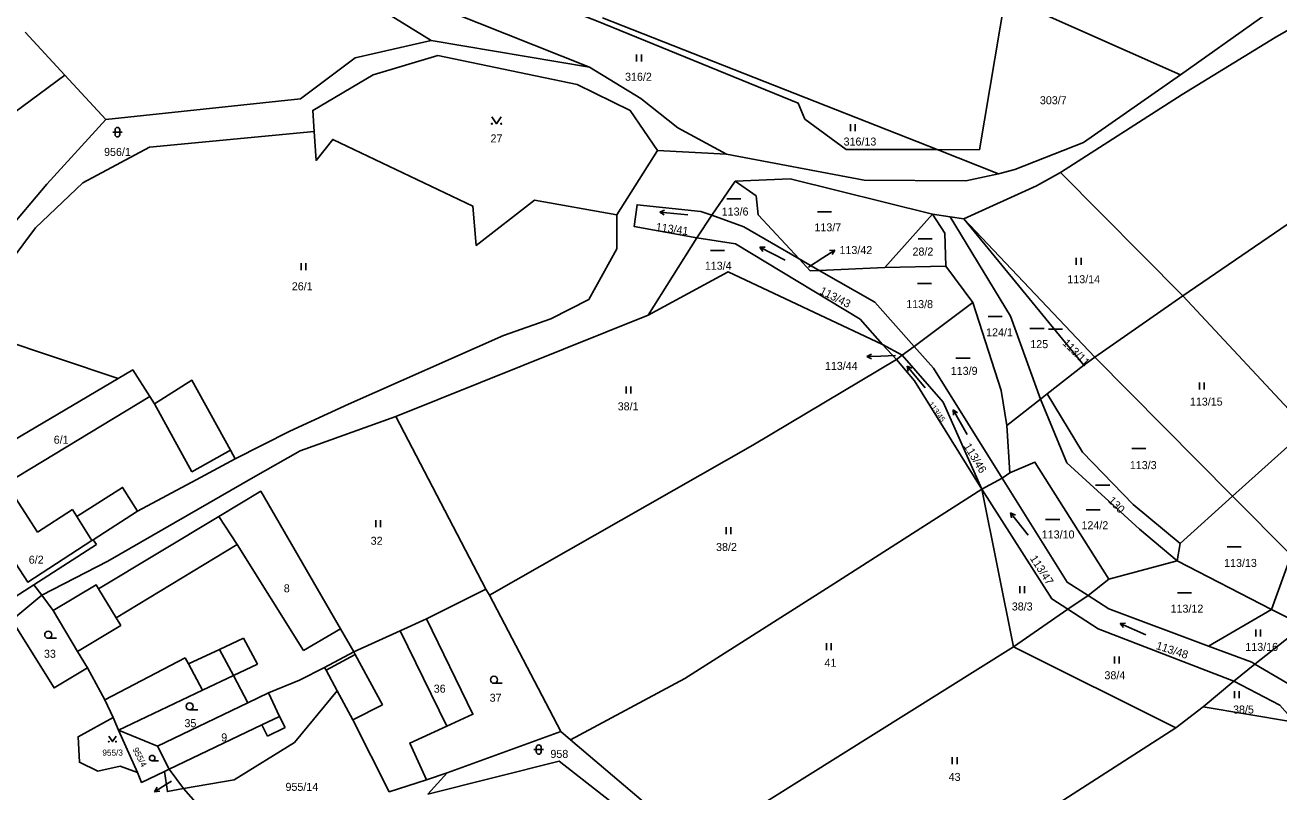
# Model space of a CAD drawing. Extents: x -751333 to -746055, y -1133395 to -1129777.
# Drawn here: x -747812.8 to -747546.5, y -1130986.6 to -1130823.7 of the extents above; entities that cross this region are included whole.
import ezdxf

# ---------------------------------------------------------------- set-up
doc = ezdxf.new("R2010")
doc.units = 0
for name, color, linetype in [('Hranice parcel', 7, 'Continuous'), ('Parcelní čísla', 7, 'Continuous'), ('Pop  PČ popisy', 7, 'Continuous'), ('Vnitřní kresba', 7, 'Continuous'), ('Značky kultur', 7, 'Continuous')]:
    doc.layers.add(name, color=color, linetype=linetype)

msp = doc.modelspace()

# ---------------------------------------------------------------- linework, layer by layer
at = {"layer": 'Hranice parcel'}
for p, q in [((-747567.45, -1130834.27), (-747601.44, -1130819.19)), ((-747690.17, -1130822.16), (-747619.1, -1130850.16)), ((-747812.81, -1130825.22), (-747804.38, -1130834.32)), ((-747692.92, -1130832.64), (-747726.57, -1130826.97)), ((-747804.38, -1130834.32), (-747840.03, -1130860.79)), ((-747804.38, -1130834.32), (-747795.63, -1130843.76)), ((-747687.14, -1130864.03), (-747678.53, -1130850.34)), ((-747678.53, -1130850.34), (-747663.88, -1130851.09)), ((-747606.08, -1130855.29), (-747619.1, -1130850.16)), ((-747566.95, -1130881.22), (-747592.89, -1130855.02)), ((-747666.96, -1130864.06), (-747662, -1130856.84)), ((-747670.15, -1130868.87), (-747666.96, -1130864.06)), ((-747620.11, -1130863.87), (-747630.22, -1130875.23)), ((-747620.11, -1130863.87), (-747616.32, -1130864.44)), ((-747616.32, -1130864.44), (-747613.42, -1130864.85)), ((-747585.62, -1130894.26), (-747613.42, -1130864.85)), ((-747613.42, -1130864.85), (-747587.99, -1130895.92)), ((-747670.15, -1130868.87), (-747680.49, -1130885.34)), ((-747648.43, -1130873.34), (-747644.19, -1130875.8)), ((-747644.19, -1130875.8), (-747630.22, -1130875.23)), ((-747630.22, -1130875.23), (-747617.27, -1130874.92)), ((-747611.5, -1130882.62), (-747617.27, -1130874.92)), ((-747585.62, -1130894.26), (-747566.95, -1130881.22)), ((-747540.5, -1130909.52), (-747566.95, -1130881.22)), ((-747624, -1130891.96), (-747611.5, -1130882.62)), ((-747734.07, -1130906.85), (-747680.49, -1130885.34)), ((-747825.73, -1130887.83), (-747793.01, -1130898.76)), ((-747627.71, -1130894.75), (-747630.73, -1130891.53)), ((-747630.73, -1130891.53), (-747626.52, -1130893.83)), ((-747626.52, -1130893.83), (-747624, -1130891.96)), ((-747627.71, -1130894.75), (-747626.52, -1130893.83)), ((-747585.62, -1130894.26), (-747587.99, -1130895.92)), ((-747556.37, -1130923.79), (-747585.62, -1130894.26)), ((-747587.99, -1130895.92), (-747595.75, -1130902.05)), ((-747604.33, -1130908.77), (-747597.18, -1130903.17)), ((-747597.18, -1130903.17), (-747595.75, -1130902.05)), ((-747714.93, -1130943.52), (-747734.07, -1130906.85)), ((-747603.65, -1130918.79), (-747604.33, -1130908.77)), ((-747556.37, -1130923.79), (-747540.5, -1130909.52)), ((-747605.27, -1130919.98), (-747603.65, -1130918.79)), ((-747609.63, -1130922.29), (-747605.27, -1130919.98)), ((-747609.63, -1130922.29), (-747602.88, -1130955.82)), ((-747567.53, -1130933.83), (-747556.37, -1130923.79)), ((-747810.2, -1130931.39), (-747802.76, -1130926.61)), ((-747798.33, -1130933.02), (-747788.95, -1130926.93)), ((-747810.92, -1130942.58), (-747797.65, -1130934.06)), ((-747798.61, -1130933.2), (-747798.33, -1130933.02)), ((-747797.65, -1130934.06), (-747798.33, -1130933.02)), ((-747567.53, -1130933.83), (-747568.14, -1130937.53)), ((-747568.14, -1130937.53), (-747582.67, -1130941.38)), ((-747548.12, -1130947.84), (-747568.14, -1130937.53)), ((-747809.25, -1130944.84), (-747810.92, -1130942.58)), ((-747587.06, -1130944.87), (-747582.67, -1130941.38)), ((-747809.25, -1130944.84), (-747806.85, -1130948.1)), ((-747727.56, -1130949.81), (-747714.93, -1130943.52)), ((-747714.21, -1130944.8), (-747714.93, -1130943.52)), ((-747699.04, -1130973.8), (-747714.21, -1130944.8)), ((-747591.34, -1130947.8), (-747587.06, -1130944.87)), ((-747602.88, -1130955.82), (-747591.34, -1130947.8)), ((-747561.51, -1130955.61), (-747548.12, -1130947.84)), ((-747544.17, -1130949.82), (-747548.12, -1130947.84)), ((-747551.66, -1130959.44), (-747542.97, -1130952.61)), ((-747670.43, -1130998.05), (-747602.88, -1130955.82)), ((-747602.88, -1130955.82), (-747568.39, -1130973)), ((-747749.19, -1130960.19), (-747743.01, -1130956.84)), ((-747556.12, -1130963.07), (-747551.66, -1130959.44)), ((-747562.63, -1130968.51), (-747556.12, -1130963.07)), ((-747765.48, -1130967.66), (-747784.66, -1130976.88)), ((-747568.39, -1130973), (-747562.63, -1130968.51)), ((-747794.11, -1130970.77), (-747792.94, -1130973.48)), ((-747788.92, -1130982.46), (-747792.94, -1130973.48)), ((-747792.94, -1130973.48), (-747784.66, -1130976.88)), ((-747723.14, -1130982.58), (-747699.04, -1130973.8)), ((-747696.99, -1130975.53), (-747699.04, -1130973.8)), ((-747784.66, -1130976.88), (-747782.22, -1130981.78)), ((-747670.43, -1130998.05), (-747696.99, -1130975.53)), ((-747783.2, -1130982.29), (-747782.22, -1130981.78)), ((-747782.22, -1130981.78), (-747779.16, -1130985.88)), ((-747727.55, -1130984.01), (-747723.14, -1130982.58)), ((-747727.26, -1130987.09), (-747723.14, -1130982.58)), ((-747774.01, -1130991.73), (-747779.16, -1130985.88))]:
    msp.add_line(p, q, dxfattribs=at)
for points in [[(-747592.89, -1130855.02), (-747567.07, -1130838.41), (-747547.35, -1130826.32), (-747527.53, -1130814.88), (-747492.89, -1130797.06), (-747472.69, -1130787.42), (-747441.69, -1130763.28), (-747417.46, -1130747.1), (-747393.87, -1130731.74)], [(-747566.95, -1130881.22), (-747540.53, -1130863.15), (-747518.65, -1130845.8), (-747451.1, -1130789.94), (-747421.34, -1130761.04), (-747390.31, -1130735.18)], [(-747726.57, -1130826.97), (-747749.62, -1130812.66), (-747757.07, -1130798.44), (-747753.28, -1130789.29)], [(-747751.97, -1130797.81), (-747746.34, -1130810.93), (-747722.32, -1130820.98), (-747692.92, -1130832.64)], [(-747518.4, -1130801.96), (-747535.86, -1130812.1), (-747550.62, -1130822.39), (-747567.45, -1130834.27)], [(-747619.1, -1130850.16), (-747638.4, -1130850.1), (-747647.23, -1130843.67), (-747648.62, -1130840.27), (-747691.42, -1130822.76), (-747716.64, -1130813.01), (-747715.36, -1130812.23)], [(-747619.1, -1130850.16), (-747610.15, -1130850.19), (-747604.68, -1130817.79)], [(-747795.63, -1130843.76), (-747754.3, -1130839.33), (-747742.68, -1130830.62), (-747726.57, -1130826.97)], [(-747678.53, -1130850.34), (-747684.28, -1130841.87), (-747695.55, -1130836.35), (-747725.17, -1130830.16), (-747738.86, -1130834.29), (-747751.71, -1130841.81), (-747751.43, -1130846.33)], [(-747692.92, -1130832.64), (-747682.03, -1130839.3), (-747674.17, -1130845.51), (-747663.88, -1130851.09)], [(-747567.45, -1130834.27), (-747588.01, -1130848.67), (-747602.62, -1130854.39), (-747606.08, -1130855.29)], [(-747831.64, -1130880.59), (-747825.65, -1130878.15), (-747808.21, -1130857.46), (-747795.63, -1130843.76)], [(-747751.43, -1130846.33), (-747786.35, -1130849.61), (-747800.53, -1130857.22), (-747810.62, -1130866.79), (-747823.91, -1130884.54), (-747825.73, -1130887.83)], [(-747687.14, -1130864.03), (-747704.65, -1130860.86), (-747717, -1130870.51), (-747717.72, -1130862.13), (-747747.45, -1130847.99), (-747751.02, -1130852.43), (-747751.43, -1130846.33)], [(-747663.88, -1130851.09), (-747634.6, -1130856.66), (-747613, -1130856.77), (-747606.08, -1130855.29)], [(-747613.42, -1130864.85), (-747598.03, -1130857.85), (-747592.89, -1130855.02)], [(-747662, -1130856.84), (-747650.32, -1130856.36), (-747620.11, -1130863.87)], [(-747648.43, -1130873.34), (-747657.11, -1130864.01), (-747657.53, -1130859.98), (-747662, -1130856.84)], [(-747670.15, -1130868.87), (-747683.44, -1130866.5), (-747682.82, -1130861.87), (-747669.33, -1130863.29), (-747666.96, -1130864.06)], [(-747768.2, -1130915.84), (-747756.58, -1130909.94), (-747744.11, -1130904.25), (-747711.23, -1130889.62), (-747701.16, -1130886.13), (-747693.1, -1130881.99), (-747687.11, -1130871.26), (-747687.14, -1130864.03)], [(-747666.96, -1130864.06), (-747660.13, -1130866.55), (-747648.43, -1130873.34)], [(-747617.27, -1130874.92), (-747617.49, -1130867.91), (-747620.11, -1130863.87)], [(-747597.18, -1130903.17), (-747603.54, -1130885.52), (-747616.32, -1130864.44)], [(-747630.73, -1130891.53), (-747635.43, -1130886.18), (-747661.9, -1130870.18), (-747670.15, -1130868.87)], [(-747648.43, -1130873.34), (-747646.1, -1130875.88), (-747644.19, -1130875.8)], [(-747680.49, -1130885.34), (-747663.47, -1130876.12), (-747630.73, -1130891.53)], [(-747644.19, -1130875.8), (-747632.37, -1130882.58), (-747624, -1130891.96)], [(-747604.33, -1130908.77), (-747605.55, -1130901.3), (-747611.5, -1130882.62)], [(-747624, -1130891.96), (-747619.89, -1130896.55), (-747605.27, -1130919.98)], [(-747714.21, -1130944.8), (-747658.27, -1130912.95), (-747627.71, -1130894.75)], [(-747609.63, -1130922.29), (-747623.92, -1130899.27), (-747627.71, -1130894.75)], [(-747609.63, -1130922.29), (-747617.8, -1130903.81), (-747626.52, -1130893.83)], [(-747786.33, -1130902.63), (-747789.93, -1130896.95), (-747793.01, -1130898.76)], [(-747793.01, -1130898.76), (-747820.31, -1130914.83), (-747821.04, -1130913.77), (-747826.88, -1130917.6)], [(-747768.2, -1130915.84), (-747769.2, -1130914.03), (-747777.39, -1130899.14), (-747785.31, -1130904.19), (-747786.33, -1130902.63)], [(-747568.14, -1130937.53), (-747576.11, -1130930.77), (-747591.59, -1130916.72), (-747597.18, -1130903.17)], [(-747595.75, -1130902.05), (-747588.22, -1130914.45), (-747577.5, -1130925.53), (-747567.53, -1130933.83)], [(-747734.07, -1130906.85), (-747754.36, -1130914.15), (-747764.38, -1130919.82), (-747795.26, -1130937.61), (-747809.25, -1130944.84)], [(-747788.95, -1130926.93), (-747776.49, -1130920.27), (-747768.2, -1130915.84)], [(-747582.67, -1130941.38), (-747598.35, -1130916.55), (-747603.65, -1130918.79)], [(-747822.35, -1130924.58), (-747816.84, -1130921.05), (-747810.2, -1130931.39)], [(-747802.76, -1130926.61), (-747801.79, -1130928.13), (-747792.11, -1130921.93), (-747788.95, -1130926.93)], [(-747605.27, -1130919.98), (-747591.5, -1130942.05), (-747587.06, -1130944.87)], [(-747743.01, -1130956.84), (-747745.82, -1130951.95), (-747762.77, -1130922.74), (-747771.66, -1130928.1), (-747797.2, -1130943.47), (-747797.72, -1130942.61), (-747806.85, -1130948.1)], [(-747696.99, -1130975.53), (-747672.66, -1130962.51), (-747641.8, -1130942.93), (-747609.63, -1130922.29)], [(-747591.34, -1130947.8), (-747594.77, -1130945.6), (-747609.63, -1130922.29)], [(-747548.12, -1130947.84), (-747543.96, -1130936.32), (-747556.37, -1130923.79)], [(-747810.92, -1130942.58), (-747816.91, -1130946.43), (-747824.59, -1130933.96), (-747819.12, -1130930.45)], [(-747819.12, -1130930.45), (-747816.13, -1130935.12), (-747816.51, -1130935.36), (-747812.22, -1130942.04), (-747798.61, -1130933.2)], [(-747809.25, -1130944.84), (-747815.62, -1130950.1), (-747806.65, -1130964.52), (-747799.54, -1130960.27)], [(-747587.06, -1130944.87), (-747582.62, -1130947.7), (-747561.51, -1130955.61)], [(-747806.85, -1130948.1), (-747801.65, -1130956.79), (-747799.54, -1130960.27)], [(-747556.12, -1130963.07), (-747584.92, -1130951.93), (-747591.34, -1130947.8)], [(-747727.56, -1130949.81), (-747733.16, -1130952.36), (-747743.01, -1130956.84)], [(-747727.55, -1130984.01), (-747731.13, -1130976.23), (-747723.26, -1130972.63), (-747717.69, -1130970.09), (-747727.56, -1130949.81)], [(-747561.51, -1130955.61), (-747552.29, -1130959.07), (-747551.66, -1130959.44)], [(-747799.54, -1130960.27), (-747795.87, -1130967.04), (-747794.11, -1130970.77)], [(-747792.94, -1130973.48), (-747775.11, -1130965.02), (-747768.52, -1130961.91), (-747765.48, -1130967.66)], [(-747765.48, -1130967.66), (-747761.14, -1130965.57), (-747754.52, -1130962.87), (-747749.19, -1130960.19)], [(-747746.53, -1130965.11), (-747748.88, -1130960.76), (-747749.19, -1130960.19)], [(-747551.66, -1130959.44), (-747542.61, -1130964.81), (-747533.86, -1130974.48), (-747529.57, -1130980.67)], [(-747533.76, -1130983.87), (-747538.28, -1130977.32), (-747546.35, -1130968.19), (-747556.12, -1130963.07)], [(-747779.16, -1130985.88), (-747768.38, -1130984.02), (-747755.59, -1130976.12), (-747746.53, -1130965.11)], [(-747746.53, -1130965.11), (-747743.17, -1130971.3), (-747735.45, -1130986.58), (-747727.55, -1130984.01)], [(-747562.63, -1130968.51), (-747544.05, -1130971.62), (-747534.58, -1130984.5)], [(-747788.92, -1130982.46), (-747792.6, -1130981.16), (-747797.32, -1130982.19), (-747801.28, -1130980.31), (-747801.56, -1130974.89), (-747794.11, -1130970.77)], [(-747647.48, -1131019.78), (-747615.24, -1131003.06), (-747568.39, -1130973)], [(-747641.15, -1131027.46), (-747677.24, -1130997.39), (-747699.35, -1130980.06), (-747727.26, -1130987.09)], [(-747783.2, -1130982.29), (-747788.06, -1130984.58), (-747788.92, -1130982.46)], [(-747779.16, -1130985.88), (-747782.56, -1130986.54), (-747783.2, -1130982.29)]]:
    msp.add_lwpolyline(points, dxfattribs=at)
at = {"layer": 'Pop  PČ popisy'}
for p, q in [((-747646.42, -1130875.1), (-747643.37, -1130873.12)), ((-747643.37, -1130873.12), (-747640.853, -1130871.486)), ((-747640.853, -1130871.486), (-747641.966, -1130871.611)), ((-747640.853, -1130871.486), (-747641.42, -1130872.451)), ((-747634.049, -1130894.115), (-747633.066, -1130893.579)), ((-747631.05, -1130894.01), (-747634.049, -1130894.115)), ((-747634.049, -1130894.115), (-747633.031, -1130894.58)), ((-747627.99, -1130893.91), (-747631.05, -1130894.01)), ((-747782.79, -1130984.99), (-747785.335, -1130986.58)), ((-747785.335, -1130986.58), (-747784.751, -1130985.625)), ((-747781.73, -1130984.34), (-747782.79, -1130984.99)), ((-747785.335, -1130986.58), (-747784.22, -1130986.474))]:
    msp.add_line(p, q, dxfattribs=at)
at = {"layer": 'Vnitřní kresba'}
for p, q in [((-747786.33, -1130902.63), (-747816.84, -1130921.05)), ((-747785.31, -1130904.19), (-747777.39, -1130918.63)), ((-747769.2, -1130914.03), (-747777.39, -1130918.63)), ((-747801.79, -1130928.13), (-747798.61, -1130933.2)), ((-747767.79, -1130934.01), (-747771.66, -1130928.1)), ((-747793.47, -1130949.63), (-747767.79, -1130934.01)), ((-747753.68, -1130956.54), (-747767.79, -1130934.01)), ((-747797.2, -1130943.47), (-747793.47, -1130949.63)), ((-747801.65, -1130956.79), (-747792.49, -1130951.26)), ((-747793.47, -1130949.63), (-747792.49, -1130951.26)), ((-747766.45, -1130953.93), (-747771.54, -1130956.35)), ((-747763.42, -1130959.49), (-747766.45, -1130953.93)), ((-747753.68, -1130956.54), (-747745.82, -1130951.95)), ((-747733.16, -1130952.36), (-747723.26, -1130972.63)), ((-747771.54, -1130956.35), (-747778.1, -1130959.43)), ((-747771.54, -1130956.35), (-747768.52, -1130961.91)), ((-747778.81, -1130958.12), (-747795.87, -1130967.04)), ((-747778.81, -1130958.12), (-747778.1, -1130959.43)), ((-747748.88, -1130960.76), (-747742.69, -1130957.41)), ((-747742.69, -1130957.41), (-747743.01, -1130956.84)), ((-747736.92, -1130968.11), (-747742.69, -1130957.41)), ((-747778.1, -1130959.43), (-747775.11, -1130965.02)), ((-747768.52, -1130961.91), (-747763.42, -1130959.49)), ((-747761.14, -1130965.57), (-747758.74, -1130970.57)), ((-747743.17, -1130971.3), (-747736.92, -1130968.11)), ((-747762.53, -1130972.38), (-747782.22, -1130981.78)), ((-747758.74, -1130970.57), (-747762.53, -1130972.38)), ((-747761.33, -1130974.79), (-747762.53, -1130972.38)), ((-747758.74, -1130970.57), (-747757.54, -1130972.91)), ((-747757.54, -1130972.91), (-747761.33, -1130974.79))]:
    msp.add_line(p, q, dxfattribs=at)
at = {"layer": 'Značky kultur'}
for p, q in [((-747682.931, -1130831.43), (-747682.931, -1130829.93)), ((-747681.93, -1130831.43), (-747681.93, -1130829.93)), ((-747637.491, -1130846.23), (-747637.491, -1130844.73)), ((-747636.49, -1130846.23), (-747636.49, -1130844.73)), ((-747794.181, -1130846.441), (-747792.179, -1130846.441)), ((-747793.681, -1130845.941), (-747793.681, -1130846.942)), ((-747792.679, -1130846.942), (-747792.679, -1130845.941)), ((-747663.768, -1130860.61), (-747660.768, -1130860.61)), ((-747678.02, -1130863.406), (-747676.996, -1130863.01)), ((-747672.053, -1130864.033), (-747678.02, -1130863.406)), ((-747678.02, -1130863.406), (-747677.1, -1130864.007)), ((-747644.548, -1130863.36), (-747641.548, -1130863.36)), ((-747656.744, -1130870.903), (-747655.646, -1130870.899)), ((-747651.398, -1130873.627), (-747656.744, -1130870.903)), ((-747656.744, -1130870.903), (-747656.101, -1130871.793)), ((-747623.168, -1130869.11), (-747620.168, -1130869.11)), ((-747667.278, -1130871.61), (-747664.278, -1130871.61)), ((-747589.561, -1130874.63), (-747589.561, -1130873.13)), ((-747588.56, -1130874.63), (-747588.56, -1130873.13)), ((-747754.201, -1130875.77), (-747754.201, -1130874.27)), ((-747753.2, -1130875.77), (-747753.2, -1130874.27)), ((-747623.278, -1130878.56), (-747620.278, -1130878.56)), ((-747608.298, -1130885.57), (-747605.298, -1130885.57)), ((-747599.418, -1130888.17), (-747596.418, -1130888.17)), ((-747595.498, -1130888.31), (-747592.498, -1130888.31)), ((-747615.128, -1130894.45), (-747612.128, -1130894.45)), ((-747621.656, -1130900.749), (-747625.513, -1130896.153)), ((-747625.513, -1130896.153), (-747625.269, -1130897.224)), ((-747625.513, -1130896.153), (-747624.501, -1130896.579)), ((-747685.151, -1130901.99), (-747685.151, -1130900.49)), ((-747684.15, -1130901.99), (-747684.15, -1130900.49)), ((-747563.381, -1130901.11), (-747563.381, -1130899.61)), ((-747562.38, -1130901.11), (-747562.38, -1130899.61)), ((-747612.711, -1130910.639), (-747615.711, -1130905.443)), ((-747615.711, -1130905.443), (-747615.657, -1130906.54)), ((-747615.711, -1130905.443), (-747614.788, -1130906.038)), ((-747577.788, -1130913.63), (-747574.788, -1130913.63)), ((-747585.468, -1130921.44), (-747582.468, -1130921.44)), ((-747599.807, -1130932.055), (-747603.501, -1130927.327)), ((-747603.501, -1130927.327), (-747603.294, -1130928.406)), ((-747603.501, -1130927.327), (-747602.504, -1130927.788)), ((-747587.498, -1130926.66), (-747584.498, -1130926.66)), ((-747738.331, -1130930.36), (-747738.331, -1130928.86)), ((-747737.33, -1130930.36), (-747737.33, -1130928.86)), ((-747596.078, -1130928.75), (-747593.078, -1130928.75)), ((-747663.891, -1130931.87), (-747663.891, -1130930.37)), ((-747662.89, -1130931.87), (-747662.89, -1130930.37)), ((-747557.528, -1130934.52), (-747554.528, -1130934.52)), ((-747601.561, -1130944.39), (-747601.561, -1130942.89)), ((-747600.56, -1130944.39), (-747600.56, -1130942.89)), ((-747568.068, -1130944.3), (-747565.068, -1130944.3)), ((-747580.243, -1130950.825), (-747579.146, -1130950.764)), ((-747574.762, -1130953.265), (-747580.243, -1130950.825)), ((-747580.243, -1130950.825), (-747579.554, -1130951.681)), ((-747807.883, -1130953.97), (-747806.133, -1130953.97)), ((-747551.411, -1130953.59), (-747551.411, -1130952.09)), ((-747550.41, -1130953.59), (-747550.41, -1130952.09)), ((-747642.631, -1130956.48), (-747642.631, -1130954.98)), ((-747641.63, -1130956.48), (-747641.63, -1130954.98)), ((-747581.471, -1130959.36), (-747581.471, -1130957.86)), ((-747580.47, -1130959.36), (-747580.47, -1130957.86)), ((-747713.223, -1130963.53), (-747711.473, -1130963.53)), ((-747555.951, -1130966.7), (-747555.951, -1130965.2)), ((-747554.95, -1130966.7), (-747554.95, -1130965.2)), ((-747777.863, -1130969.18), (-747776.113, -1130969.18)), ((-747704.731, -1130977.601), (-747702.729, -1130977.601)), ((-747704.231, -1130977.101), (-747704.231, -1130978.102)), ((-747703.229, -1130978.102), (-747703.229, -1130977.101)), ((-747785.815, -1130980), (-747784.467, -1130980)), ((-747615.891, -1130980.72), (-747615.891, -1130979.22)), ((-747614.89, -1130980.72), (-747614.89, -1130979.22))]:
    msp.add_line(p, q, dxfattribs=at)
for points in [[(-747713.68, -1130843.159), (-747712.68, -1130844.66), (-747711.68, -1130843.159)], [(-747795.02, -1130974.764), (-747794.25, -1130975.92), (-747793.48, -1130974.764)]]:
    msp.add_lwpolyline(points, dxfattribs=at)
for centre, radius in [((-747713.68, -1130844.659), 0.1), ((-747711.68, -1130844.659), 0.1), ((-747807.883, -1130953.22), 0.75), ((-747713.223, -1130962.78), 0.75), ((-747777.863, -1130968.43), 0.75), ((-747795.02, -1130975.92), 0.077), ((-747793.48, -1130975.92), 0.077), ((-747785.815, -1130979.422), 0.577)]:
    msp.add_circle(centre, radius, dxfattribs=at)
for centre, start, end in [((-747793.18, -1130845.941), 0, 180), ((-747793.18, -1130846.941), 180, 359.98789), ((-747703.73, -1130977.101), 0, 180), ((-747703.73, -1130978.101), 180, 359.98789)]:
    msp.add_arc(centre, 0.5, start, end, dxfattribs=at)

# ---------------------------------------------------------------- texts
at = {"layer": 'Parcelní čísla'}
for s, height, p in [('316/2', 1.7, (-747685.39, -1130835.52)), ('303/7', 1.7, (-747597.29, -1130840.51)), ('27', 1.7, (-747713.96, -1130848.62)), ('956/1', 1.7, (-747796.03, -1130851.49)), ('316/13', 1.7, (-747638.98, -1130849.29)), ('113/6', 1.7, (-747664.86, -1130864.16)), ('113/7', 1.7, (-747645.17, -1130867.51)), ('113/42', 1.7, (-747639.85, -1130872.34)), ('28/2', 1.7, (-747624.34, -1130872.66)), ('113/4', 1.7, (-747668.45, -1130875.67)), ('113/14', 1.7, (-747591.46, -1130878.54)), ('26/1', 1.7, (-747756.16, -1130880.04)), ('113/8', 1.7, (-747625.68, -1130883.82)), ('124/1', 1.7, (-747608.71, -1130889.82)), ('125', 1.7, (-747599.33, -1130892.33)), ('113/44', 1.7, (-747642.945, -1130896.948)), ('113/9', 1.7, (-747616.22, -1130898)), ('113/15', 1.7, (-747565.43, -1130904.54)), ('38/1', 1.7, (-747686.95, -1130905.54)), ('6/1', 1.7, (-747806.72, -1130912.63)), ('113/3', 1.7, (-747578.19, -1130918.03)), ('124/2', 1.7, (-747588.46, -1130930.8)), ('32', 1.7, (-747739.41, -1130934.1)), ('113/10', 1.7, (-747596.89, -1130932.76)), ('38/2', 1.7, (-747666.06, -1130935.42)), ('6/2', 1.7, (-747812.02, -1130938.12)), ('113/13', 1.7, (-747558.17, -1130938.81)), ('8', 1.7, (-747757.86, -1130944.2)), ('38/3', 1.7, (-747603.26, -1130948.06)), ('113/12', 1.7, (-747569.54, -1130948.52)), ('33', 1.7, (-747808.79, -1130958.11)), ('113/16', 1.7, (-747553.66, -1130956.65)), ('41', 1.7, (-747643.03, -1130960.03)), ('38/4', 1.7, (-747583.58, -1130962.67)), ('36', 1.7, (-747726.02, -1130965.52)), ('37', 1.7, (-747714.15, -1130967.45)), ('38/5', 1.7, (-747556.27, -1130969.95)), ('35', 1.7, (-747778.96, -1130972.85)), ('9', 1.7, (-747771.15, -1130975.87)), ('955/3', 1.304, (-747796.39, -1130978.912)), ('958', 1.7, (-747701.24, -1130979.38)), ('43', 1.7, (-747616.67, -1130984.27)), ('955/14', 1.7, (-747757.5, -1130986.38))]:
    msp.add_text(s, height=height, dxfattribs=at).set_placement(p)
for s, height, rotation, p in [('113/41', 1.7, 352, (-747678.948, -1130867.361)), ('113/43', 1.7, 333, (-747644.225, -1130880.687)), ('113/11', 1.7, 315, (-747592.631, -1130891.391)), ('113/45', 1.14, 306, (-747621.031, -1130904.235)), ('113/46', 1.7, 301, (-747613.538, -1130913.127)), ('130', 1.7, 314, (-747582.941, -1130924.84)), ('113/47', 1.7, 303, (-747599.482, -1130936.992)), ('113/48', 1.7, 342, (-747572.752, -1130956.218)), ('955/4', 1.304, 297, (-747790.02, -1130977.566))]:
    msp.add_text(s, height=height, rotation=rotation, dxfattribs=at).set_placement(p)

doc.saveas('drawing.dxf')
